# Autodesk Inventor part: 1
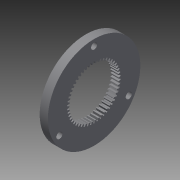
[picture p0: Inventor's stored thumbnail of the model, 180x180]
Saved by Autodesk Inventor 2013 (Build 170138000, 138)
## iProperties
Created: 2012-07
Part Number: 1
Material: Messing, weicher Gelbton
Vendor: maedler.de
Document SubType Name: Modeling
Designer: rYan
Mass: 36.461 g
Surface Area: 34.7249 cm^2
Volume: 4.30472 cm^3
Density: 8.47 g/cm^3
Übersetzungsnorm: STEP AP214IS
Dateiname: c:/PPEXPORT/antriebselemente_und_normteile/innenkraenze/artikel_nr___26145000.stp
Postprozessor: Build: 138, Release: 2013 RTM - Date: Thu 03/01/2012
Gesendete Einheiten: Millimeter
Unbestimmtheit: 1.0000000000000002e-06
Author: rYan
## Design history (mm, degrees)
node "11"
sketch "Skizze1"
  geometry: L1 (31.5, 0)-(-31.5, 0) reference; C1 r 1.5 at (-8.829, 17.387) reference; A1 r 13.05 centre (0, 0) between (-3.774, 12.492) and (-4.289, 12.325) reference; 2 further points
  constraints: 1 centre point, 1 point on line, 1 other
  dimensions: "d11" = 19.5 distance of A1.centre point (-19.5, 0)
hole "Bohrung1" sketch "Skizze1" at (-19.5, 0) diameter "d0" = 3; stored, may be unused: countersink angle "d4" = 90 deg, drill point angle "d6" = 118 deg; dims "d1" = 6, "d2" = 4, "d3" = 2, "d5" = 8
pattern_circular "Runde Anordnung1" dims angle "d8" = 360 deg
node "1"
node "Basis1"
